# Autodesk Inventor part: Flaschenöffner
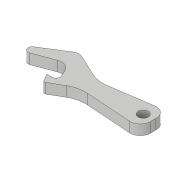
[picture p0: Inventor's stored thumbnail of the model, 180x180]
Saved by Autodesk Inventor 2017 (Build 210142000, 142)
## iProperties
Created: 2016-09
Part Number: Flaschenöffner
Material: Generic
Document SubType Name: Modeling
Designer: e_krauts
Density: 1 g/cm^3
Appearance: Default
Author: e_krauts
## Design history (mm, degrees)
sketch "Skizze1"
  geometry: L1 (6.975, 0)-(-25.896, 0) reference; L2 (-20.906, 3.385)-(-0.732, 6.4); L3 (-22.792, -4.858)-(-0.345, -6.428); L4 (0, 15.153)-(0, -16.516) reference; L5 (4.94, 1.117)-(4.94, -1.499) reference; L6 (-37.693, -10.5)-(-31.338, -6.831); L7 (-25.896, 0)-(-62.56, 0); L8 (-39.059, -10.134)-(-40.916, -6.917); L9 (-40.729, -6.618)-(-38.618, -6.765); L10 (-41.104, -6.591)-(-38.988, -6.591); L11 (-36.659, -3.938)-(-38.121, -0.742); L12 (-44.427, 1.859)-(-54.356, -1.872); L13 (-56.121, 1.695)-(-43.904, 9.346); L14 (-40.09, 9.581)-(-29.463, 4.625); L15 (-42.061, 10.5)-(-23.641, 10.5); C1 r 2.5 at (0, 0); A1 r 4.955 centre (0, 1.499) between (4.94, 1.117) and (-0.732, 6.4); A2 r 4.94 centre (0, -1.499) between (-0.345, -6.428) and (4.94, -1.499); A3 r 2 centre (-55.06, 0) between (-56.121, 1.695) and (-54.356, -1.872); A4 r 15 centre (-23.123, 18.22) between (-29.463, 4.625) and (-20.906, 3.385); A5 r 15 centre (-23.838, -19.821) between (-22.792, -4.858) and (-31.338, -6.831); A6 r 4 centre (-41.781, 5.956) between (-40.09, 9.581) and (-43.904, 9.346); A7 r 5 centre (-42.668, -2.821) between (-38.121, -0.742) and (-44.427, 1.859); A8 r 2 centre (-38.478, -4.77) between (-38.618, -6.765) and (-36.659, -3.938); A9 r 1 centre (-38.193, -9.634) between (-39.059, -10.134) and (-37.693, -10.5); A10 r 0.2 centre (-40.743, -6.817) between (-40.729, -6.618) and (-40.916, -6.917); 4 further points
  constraints: 30 end point, 20 point on circle, 19 tangent, 13 point on line, 11 centre point, 5 horizontal, 2 vertical, 1 coincident, 1 equal length, 1 symmetric about line, 1 other
  dimensions: "d0" = 5 diameter of C1; "d4" = 8.5 deg angle of L1 L2; "d5" = 4 deg angle of L1 L3; "d6" = 30 deg angle of L7 L6; "d7" = 43.5 distance from line of L5 point (-38.559, -11); "d8" = 11 distance from line of L7 point (-38.559, -11); "d9" = 4 deg angle of L9 L10; "d15" = 7 distance from line of L7 point (-35.259, -7); "d17" = 40.2 distance from line of L5 point (-35.259, -7); "d18" = 3.5 distance from line of L7 point (-40.06, 3.5); "d19" = 45 distance from line of L5 point (-40.06, 3.5); "d20" = 4 diameter of A3; "d21" = 60 distance from line of L5 A3.centre; "d22" = 10.5 distance from line of L7 L15.start; "d23" = 47 distance from line of L5 L15.start; "d24" = 25 deg angle of L14 L15; "d25" = 15 radius of A4; "d26" = 15 radius of A5 (derived); "d27" = 4 radius of A6; "d28" = 5 radius of A7; "d29" = 2 radius of A8; "d30" = 1 radius of A9; "d31" = 0.2 radius of A10; "d34" = 30 deg angle of L4 L8
extrude "Extrusion1" new body sketch "Skizze1" distance "d32" = 5; taper "d33" = 0 deg
node "Volumenkörper1"
other parameters: "d3" = 13
